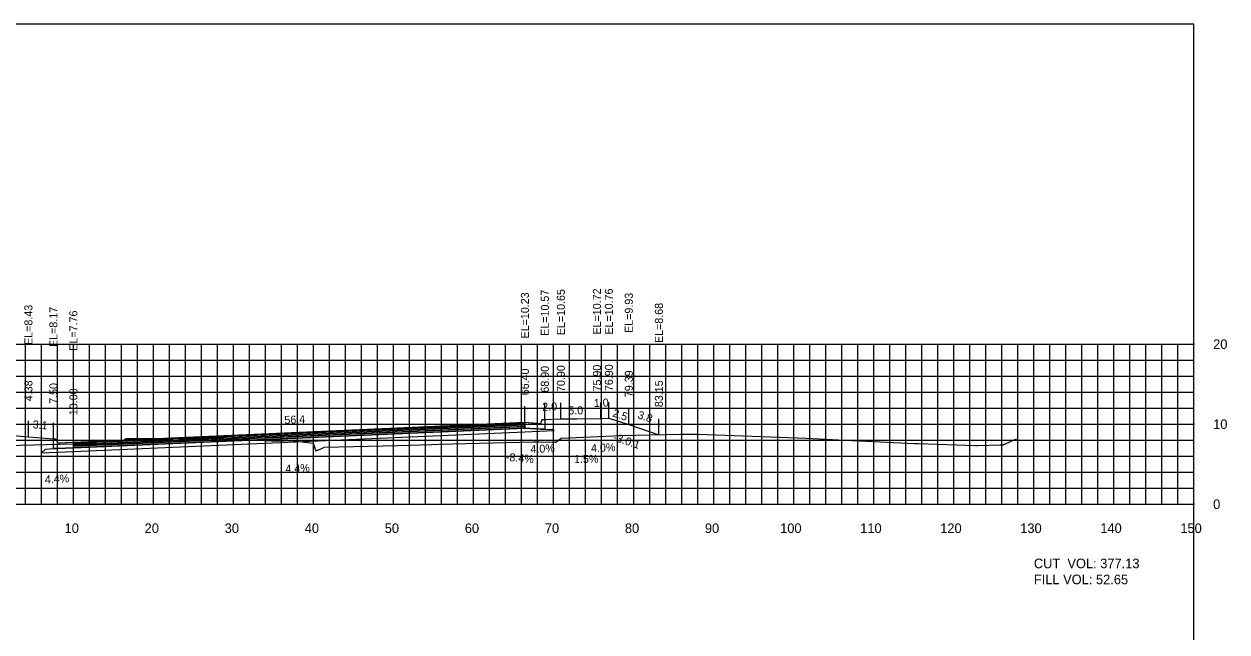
# Model space of a CAD drawing. Extents: x 1797419 to 1809236, y 248759 to 251512.
# Drawn here: x 1806034.8 to 1806185.1, y 250193.5 to 250269.4 of the extents above; entities that cross this region are included whole.
import ezdxf

# ---------------------------------------------------------------- set-up
doc = ezdxf.new("R2010")
doc.units = 0
for name, color, linetype in [('10', 7, 'Continuous'), ('3', 7, 'Continuous'), ('31', 7, 'Continuous'), ('4', 7, 'Continuous'), ('60', 7, 'Continuous'), ('ANNO-TXT', 7, 'Continuous'), ('BASE', 7, 'Continuous'), ('CL-CNST', 7, 'Continuous'), ('Level 62', 7, 'Continuous'), ('LOWER BINDER', 7, 'Continuous'), ('M-ROADS', 7, 'Continuous'), ('UPPER BINDER', 7, 'Continuous'), ('WEARING', 7, 'Continuous')]:
    doc.layers.add(name, color=color, linetype=linetype)

msp = doc.modelspace()

# ---------------------------------------------------------------- linework, layer by layer
for p, q in [((1806097.41, 250219.67), (1806097.41, 250221.67)), ((1806099.9, 250220), (1806099.9, 250222)), ((1806101.9, 250220.08), (1806101.9, 250222.08)), ((1806106.9, 250220.15), (1806106.9, 250222.15)), ((1806107.9, 250220.19), (1806107.9, 250222.19)), ((1806110.39, 250219.37), (1806110.39, 250221.37)), ((1806035.38, 250217.86), (1806035.38, 250219.86)), ((1806114.15, 250218.11), (1806114.15, 250220.11)), ((1806038.5, 250217.6), (1806038.5, 250219.6)), ((1806041, 250217.19), (1806041, 250219.19)), ((1806041, 250217.19), (1806041, 250219.19))]:
    msp.add_line(p, q)
for points in [[(1805881, 250079.43), (1806181, 250079.43), (1806181, 250269.43), (1805881, 250269.43)], [(1806097.41, 250219.67), (1806099.41, 250219.5), (1806099.57, 250220), (1806099.9, 250220), (1806099.9, 250218.79), (1806099.41, 250218.79), (1806097.41, 250218.95)], [(1806038.5, 250217.6), (1806038.83, 250217.6), (1806039, 250217.1), (1806041, 250217.19), (1806041, 250216.47), (1806039, 250216.38), (1806038.5, 250216.38)]]:
    msp.add_lwpolyline(points, close=True)
at = {"layer": '60'}
for p, q in [((1806181, 250209.43), (1806181, 250229.43)), ((1806181.06, 250229.43), (1806181, 250229.43)), ((1806181.06, 250219.43), (1806181, 250219.43)), ((1805881, 250209.43), (1806181, 250209.43)), ((1806041, 250209.37), (1806041, 250209.43)), ((1806051, 250209.37), (1806051, 250209.43)), ((1806061, 250209.37), (1806061, 250209.43)), ((1806071, 250209.37), (1806071, 250209.43)), ((1806081, 250209.37), (1806081, 250209.43)), ((1806091, 250209.37), (1806091, 250209.43)), ((1806101, 250209.37), (1806101, 250209.43)), ((1806111, 250209.37), (1806111, 250209.43)), ((1806121, 250209.37), (1806121, 250209.43)), ((1806131, 250209.37), (1806131, 250209.43)), ((1806141, 250209.37), (1806141, 250209.43)), ((1806151, 250209.37), (1806151, 250209.43)), ((1806161, 250209.37), (1806161, 250209.43)), ((1806171, 250209.37), (1806171, 250209.43)), ((1806181, 250209.37), (1806181, 250209.43)), ((1806181.06, 250209.43), (1806181, 250209.43))]:
    msp.add_line(p, q, dxfattribs=at)
at = {"layer": 'BASE'}
msp.add_lwpolyline([(1806041, 250216.47), (1806097.41, 250218.95), (1806099.41, 250218.79), (1806099.9, 250218.79), (1806100.9, 250218.76), (1806101.06, 250218.61), (1806097.41, 250218.45), (1806041, 250215.97), (1806036.99, 250215.8), (1806037.5, 250216.31), (1806038.5, 250216.38), (1806039, 250216.38)], close=True, dxfattribs=at)
at = {"layer": 'CL-CNST'}
msp.add_lwpolyline([(1806031, 250218.22), (1806035.38, 250217.86), (1806038.5, 250217.6), (1806038.83, 250217.6), (1806038.96, 250217.21), (1806039, 250217.1), (1806039.29, 250217.12), (1806041, 250217.19), (1806041, 250217.19), (1806097.41, 250219.67), (1806098.23, 250219.6), (1806099.41, 250219.5), (1806099.57, 250219.99), (1806099.57, 250220), (1806099.9, 250220), (1806100.04, 250220), (1806101.9, 250220.08), (1806103.88, 250220.11), (1806106.9, 250220.15), (1806107.9, 250220.19), (1806110.39, 250219.37), (1806114.15, 250218.11)], dxfattribs=at)
at = {"layer": 'Level 62'}
for p, q in [((1805881, 250229.43), (1806181, 250229.43)), ((1806035, 250209.43), (1806035, 250229.43)), ((1806037, 250209.43), (1806037, 250229.43)), ((1806039, 250209.43), (1806039, 250229.43)), ((1806041, 250209.43), (1806041, 250229.43)), ((1806043, 250209.43), (1806043, 250229.43)), ((1806045, 250209.43), (1806045, 250229.43)), ((1806047, 250209.43), (1806047, 250229.43)), ((1806049, 250209.43), (1806049, 250229.43)), ((1806051, 250209.43), (1806051, 250229.43)), ((1806053, 250209.43), (1806053, 250229.43)), ((1806055, 250209.43), (1806055, 250229.43)), ((1806057, 250209.43), (1806057, 250229.43)), ((1806059, 250209.43), (1806059, 250229.43)), ((1806061, 250209.43), (1806061, 250229.43)), ((1806063, 250209.43), (1806063, 250229.43)), ((1806065, 250209.43), (1806065, 250229.43)), ((1806067, 250209.43), (1806067, 250229.43)), ((1806069, 250209.43), (1806069, 250229.43)), ((1806071, 250209.43), (1806071, 250229.43)), ((1806073, 250209.43), (1806073, 250229.43)), ((1806075, 250209.43), (1806075, 250229.43)), ((1806077, 250209.43), (1806077, 250229.43)), ((1806079, 250209.43), (1806079, 250229.43)), ((1806081, 250209.43), (1806081, 250229.43)), ((1806083, 250209.43), (1806083, 250229.43)), ((1806085, 250209.43), (1806085, 250229.43)), ((1806087, 250209.43), (1806087, 250229.43)), ((1806089, 250209.43), (1806089, 250229.43)), ((1806091, 250209.43), (1806091, 250229.43)), ((1806093, 250209.43), (1806093, 250229.43)), ((1806095, 250209.43), (1806095, 250229.43)), ((1806097, 250209.43), (1806097, 250229.43)), ((1806099, 250209.43), (1806099, 250229.43)), ((1806101, 250209.43), (1806101, 250229.43)), ((1806103, 250209.43), (1806103, 250229.43)), ((1806105, 250209.43), (1806105, 250229.43)), ((1806107, 250209.43), (1806107, 250229.43)), ((1806109, 250209.43), (1806109, 250229.43)), ((1806111, 250209.43), (1806111, 250229.43)), ((1806113, 250209.43), (1806113, 250229.43)), ((1806115, 250209.43), (1806115, 250229.43)), ((1806117, 250209.43), (1806117, 250229.43)), ((1806119, 250209.43), (1806119, 250229.43)), ((1806121, 250209.43), (1806121, 250229.43)), ((1806123, 250209.43), (1806123, 250229.43)), ((1806125, 250209.43), (1806125, 250229.43)), ((1806127, 250209.43), (1806127, 250229.43)), ((1806129, 250209.43), (1806129, 250229.43)), ((1806131, 250209.43), (1806131, 250229.43)), ((1806133, 250209.43), (1806133, 250229.43)), ((1806135, 250209.43), (1806135, 250229.43)), ((1806137, 250209.43), (1806137, 250229.43)), ((1806139, 250209.43), (1806139, 250229.43)), ((1806141, 250209.43), (1806141, 250229.43)), ((1806143, 250209.43), (1806143, 250229.43)), ((1806145, 250209.43), (1806145, 250229.43)), ((1806147, 250209.43), (1806147, 250229.43)), ((1806149, 250209.43), (1806149, 250229.43)), ((1806151, 250209.43), (1806151, 250229.43)), ((1806153, 250209.43), (1806153, 250229.43)), ((1806155, 250209.43), (1806155, 250229.43)), ((1806157, 250209.43), (1806157, 250229.43)), ((1806159, 250209.43), (1806159, 250229.43)), ((1806161, 250209.43), (1806161, 250229.43)), ((1806163, 250209.43), (1806163, 250229.43)), ((1806165, 250209.43), (1806165, 250229.43)), ((1806167, 250209.43), (1806167, 250229.43)), ((1806169, 250209.43), (1806169, 250229.43)), ((1806171, 250209.43), (1806171, 250229.43)), ((1806173, 250209.43), (1806173, 250229.43)), ((1806175, 250209.43), (1806175, 250229.43)), ((1806177, 250209.43), (1806177, 250229.43)), ((1806179, 250209.43), (1806179, 250229.43)), ((1806181, 250209.43), (1806181, 250229.43)), ((1805881, 250227.43), (1806181, 250227.43)), ((1805881, 250225.43), (1806181, 250225.43)), ((1805881, 250223.43), (1806181, 250223.43)), ((1805881, 250221.43), (1806181, 250221.43)), ((1805881, 250219.43), (1806181, 250219.43)), ((1805881, 250217.43), (1806181, 250217.43)), ((1805881, 250215.43), (1806181, 250215.43)), ((1805881, 250213.43), (1806181, 250213.43)), ((1805881, 250211.43), (1806181, 250211.43)), ((1805881, 250209.43), (1806181, 250209.43))]:
    msp.add_line(p, q, dxfattribs=at)
at = {"layer": 'LOWER BINDER'}
for points in [[(1806041, 250216.85), (1806097.41, 250219.33), (1806097.41, 250219.14), (1806041, 250216.67)], [(1806041, 250216.67), (1806097.41, 250219.14), (1806097.41, 250218.95), (1806041, 250216.47)]]:
    msp.add_lwpolyline(points, close=True, dxfattribs=at)
at = {"layer": 'M-ROADS'}
msp.add_lwpolyline([(1806032.73, 250216.78), (1806040.93, 250216.97), (1806045.16, 250217.06), (1806045.4, 250217.06), (1806045.84, 250217.09), (1806046.05, 250217.1), (1806046.23, 250217.09), (1806046.24, 250217.09), (1806046.44, 250217.12), (1806046.5, 250217.13), (1806046.55, 250217.13), (1806046.59, 250217.13), (1806046.62, 250217.14), (1806046.63, 250217.14), (1806046.68, 250217.12), (1806046.72, 250217.13), (1806046.73, 250217.13), (1806046.75, 250217.12), (1806046.75, 250217.12), (1806046.77, 250217.13), (1806046.78, 250217.14), (1806046.79, 250217.14), (1806046.79, 250217.14), (1806046.8, 250217.13), (1806046.81, 250217.13), (1806046.82, 250217.13), (1806046.82, 250217.13), (1806046.83, 250217.14), (1806046.84, 250217.14), (1806046.84, 250217.14), (1806046.85, 250217.14), (1806046.85, 250217.14), (1806046.85, 250217.14), (1806046.86, 250217.14), (1806046.86, 250217.14), (1806046.87, 250217.14), (1806046.87, 250217.14), (1806046.87, 250217.14), (1806046.88, 250217.14), (1806046.88, 250217.14), (1806046.88, 250217.14), (1806046.88, 250217.14), (1806047.52, 250217.6), (1806047.53, 250217.6), (1806047.53, 250217.6), (1806047.53, 250217.6), (1806047.53, 250217.6), (1806047.54, 250217.6), (1806047.54, 250217.6), (1806047.54, 250217.6), (1806047.55, 250217.6), (1806047.55, 250217.61), (1806047.56, 250217.63), (1806047.7, 250217.65), (1806047.73, 250217.65), (1806052.04, 250217.63), (1806052.25, 250217.63), (1806056.26, 250217.66), (1806058.93, 250217.8), (1806059.04, 250217.79), (1806059.51, 250217.77), (1806061.69, 250217.57), (1806062.74, 250217.51), (1806066.46, 250217.29), (1806068.1, 250217.4), (1806070.97, 250217.04), (1806071.14, 250216.54), (1806071.27, 250216.08), (1806072.04, 250216.41), (1806072.32, 250216.54), (1806081.55, 250216.78), (1806084.32, 250216.85), (1806085.76, 250216.91), (1806086.64, 250216.94), (1806086.64, 250216.94), (1806098.49, 250217.22), (1806099.13, 250217.23), (1806101.13, 250217.2), (1806101.17, 250217.2), (1806101.29, 250217.19), (1806101.93, 250217.68), (1806101.95, 250217.69), (1806107.53, 250217.93), (1806109.39, 250218), (1806116.77, 250218.17), (1806117.6, 250218.2), (1806117.66, 250218.2), (1806118.21, 250218.2), (1806118.31, 250218.2), (1806118.47, 250218.2), (1806119.02, 250218.2), (1806131.48, 250217.72), (1806132.55, 250217.69), (1806136.58, 250217.47), (1806146.08, 250217.01), (1806146.37, 250217), (1806146.6, 250217), (1806153.71, 250216.75), (1806153.98, 250216.75), (1806156.78, 250216.84), (1806157.05, 250216.84), (1806157.16, 250216.84), (1806158.84, 250217.61)], dxfattribs=at)
at = {"layer": 'UPPER BINDER'}
msp.add_lwpolyline([(1806041, 250217.04), (1806097.41, 250219.52), (1806097.41, 250219.33), (1806041, 250216.85)], close=True, dxfattribs=at)
at = {"layer": 'WEARING'}
msp.add_lwpolyline([(1806041, 250217.19), (1806097.41, 250219.67), (1806097.41, 250219.52), (1806041, 250217.04)], close=True, dxfattribs=at)

# ---------------------------------------------------------------- texts
msp.add_text('-3.0:1', height=1, rotation=341.5671).set_placement((1806108.35, 250217.41))
at = {"layer": '10'}
for s, p in [('10', (1806039.9, 250205.83)), ('20', (1806049.9, 250205.83)), ('30', (1806059.9, 250205.83)), ('40', (1806069.9, 250205.83)), ('50', (1806079.9, 250205.83)), ('60', (1806089.9, 250205.83)), ('70', (1806099.9, 250205.83)), ('80', (1806109.9, 250205.83)), ('90', (1806119.9, 250205.83)), ('100', (1806129.3, 250205.83)), ('110', (1806139.3, 250205.83)), ('120', (1806149.3, 250205.83)), ('130', (1806159.3, 250205.83)), ('140', (1806169.3, 250205.83)), ('150', (1806179.3, 250205.83))]:
    msp.add_text(s, height=1.2, dxfattribs=at).set_placement(p)
at = {"layer": '3'}
for s, p in [('EL=10.65', (1806102.4, 250230.55)), ('EL=10.72', (1806106.91, 250230.63)), ('EL=10.76', (1806108.4, 250230.62)), ('EL=10.23', (1806097.91, 250230.14)), ('EL=10.57', (1806100.4, 250230.47)), ('EL=9.93', (1806110.89, 250230.83)), ('EL=8.43', (1806035.88, 250229.33)), ('EL=8.17', (1806039, 250229.07)), ('EL=7.76', (1806041.5, 250228.61)), ('EL=7.76', (1806041.5, 250228.61)), ('EL=8.68', (1806114.65, 250229.57)), ('66.40', (1806097.91, 250223.04)), ('68.90', (1806100.4, 250223.37)), ('70.90', (1806102.4, 250223.45)), ('75.90', (1806106.91, 250223.52)), ('76.90', (1806108.4, 250223.56)), ('79.39', (1806110.89, 250222.81)), ('4.38', (1806035.88, 250222.3)), ('7.50', (1806039, 250221.97)), ('83.15', (1806114.65, 250221.56)), ('10.00', (1806041.5, 250220.56)), ('10.00', (1806041.5, 250220.56))]:
    msp.add_text(s, height=1, rotation=90, dxfattribs=at).set_placement(p)
at = {"layer": '31'}
for s, p in [('20', (1806183.4, 250228.83)), ('10', (1806183.4, 250218.83)), ('0', (1806183.4, 250208.83))]:
    msp.add_text(s, height=1.2, dxfattribs=at).set_placement(p)
at = {"layer": '4'}
for s, rotation, p in [('2.0', 2.2897, (1806099.6, 250221.09)), ('5.0', 0.8594, (1806102.84, 250220.64)), ('1.0', 2.2923, (1806106.04, 250221.57)), ('2.5', 341.5671, (1806108.28, 250220.42)), ('3.1', 355.3051, (1806035.88, 250218.92)), ('56.4', 2.5105, (1806067.38, 250219.45)), ('3.8', 341.5671, (1806111.4, 250220.19)), ('4.0%', 2.2897, (1806098.12, 250215.82)), ('4.0%', 2.2923, (1806105.69, 250215.94)), ('-8.4%', 355.2266, (1806095, 250214.85)), ('1.5%', 0.8594, (1806103.55, 250214.57)), ('4.4%', 2.5105, (1806067.51, 250213.35)), ('4.4%', 2.519, (1806037.45, 250212.03))]:
    msp.add_text(s, height=1, rotation=rotation, dxfattribs=at).set_placement(p)
at = {"layer": 'ANNO-TXT'}
for s, p in [('CUT  VOL: 377.13', (1806161, 250201.43)), ('FILL VOL: 52.65', (1806161, 250199.43))]:
    msp.add_text(s, height=1.2, dxfattribs=at).set_placement(p)

doc.saveas('drawing.dxf')
